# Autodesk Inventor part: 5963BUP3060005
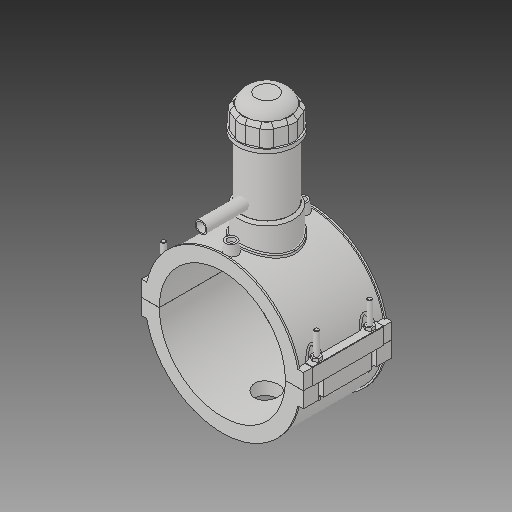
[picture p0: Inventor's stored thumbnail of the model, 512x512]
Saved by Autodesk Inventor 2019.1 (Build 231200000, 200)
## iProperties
Created: 2017-07
Part Number: 5963BUP3060005
Material: Generic
Description: PLASSON TAPPING SADDLE 6''IPS x 1/2''CTS
Document SubType Name: Modeling
Designer: KIM
Density: 1 g/cm^3
Appearance: Default
Author: KIM
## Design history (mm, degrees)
derived "5963BBP_5963BUP.ipt"
feature "Solid1::5963BBP_5963BUP.ipt"
feature "Solid2::5963BBP_5963BUP.ipt"
feature "Solid3::5963BBP_5963BUP.ipt"
tag "TaggingFeature1"
body "Solid1"
body "Solid2"
body "Solid3"
other parameters: "d0" = 168, "d2" = 215.9, "d3" = 42, "d4" = 118.11, "d5" = 0, "d6" = 0.1, "d8" = 0, "d19" = 6, "d20" = 6, "d21" = 70.866, "d23" = 0, "d24" = 35.433, "d26" = 0, "d27" = 3, "d28" = 3, "d29" = 3, "d30" = 56, "d31" = 6, "d32" = 0, "d33" = 0, "d34" = 0.6, "d40" = 104.832, "d41" = 75.6, "d43" = 0, "d45" = 0, "d47" = 171.666, "d70" = 15, "d72" = 0, "d73" = 6, "d75" = 5, "d76" = 0, "d77" = 8.4, "d78" = 114, "d79" = 15, "d80" = 47.244, "d82" = 5 deg, "d84" = 4, "d85" = 14, "d86" = 0, "d87" = 3, "d88" = 0, "d89" = 1, "d90" = 1, "d91" = 94.488, "d92" = 0, "d93" = 0.5, "d94" = 88.42105, "d96" = 205.632, "d97" = 2.3622, "d98" = 0, "d102" = 1.68, "d120" = 140 deg, "d121" = 24.228, "d122" = 20 deg, "d123" = 403.2, "d124" = 120.96, "d126" = 0, "d143" = 173.04, "d145" = 25.84615, "d149" = 2.52, "d150" = 28.43077, "d153" = 118.11, "d154" = 0, "d156" = 100.8, "d157" = 160 deg, "d159" = 6.72, "d161" = 2.52, "d162" = 70.866, "d163" = 0, "d164" = 84, "d167" = 16.8, "d168" = 98.34146, "d170" = 3.2805, "d172" = 0, "d173" = 1, "d175" = 84, "d176" = 20 deg, "d177" = 11.76, "d178" = 33.6, "d180" = 0, "d183" = 13.44, "d184" = 9.408, "d185" = 38.38575, "d186" = 38.38575, "d187" = 100.8, "d188" = 10.08, "d189" = 11.76, "d190" = 0, "d191" = 151.2, "d193" = 6.9984, "d194" = 4.13385, "d195" = 90 deg, "d197" = 0, "d199" = 0, "d200" = 16.8, "d202" = 0, "d203" = 177.038, "d204" = 71.82, "d205" = 52.92, "d206" = 64.26, "d207" = 132.7785, "d208" = 138.08964, "d209" = 164.64534, "d210" = 65.016, "d211" = 75.6, "d212" = 60.48, "d213" = 51.4116, "d216" = 0, "d217" = 16.8, "d218" = 16.8, "d219" = 3.36, "d222" = 168, "d224" = 0, "d225" = 65.024, "d226" = 15.8, "d227" = 12.64, "d228" = 87.376, "d230" = 5.04, "d_" = 168, "B_" = 215.9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
